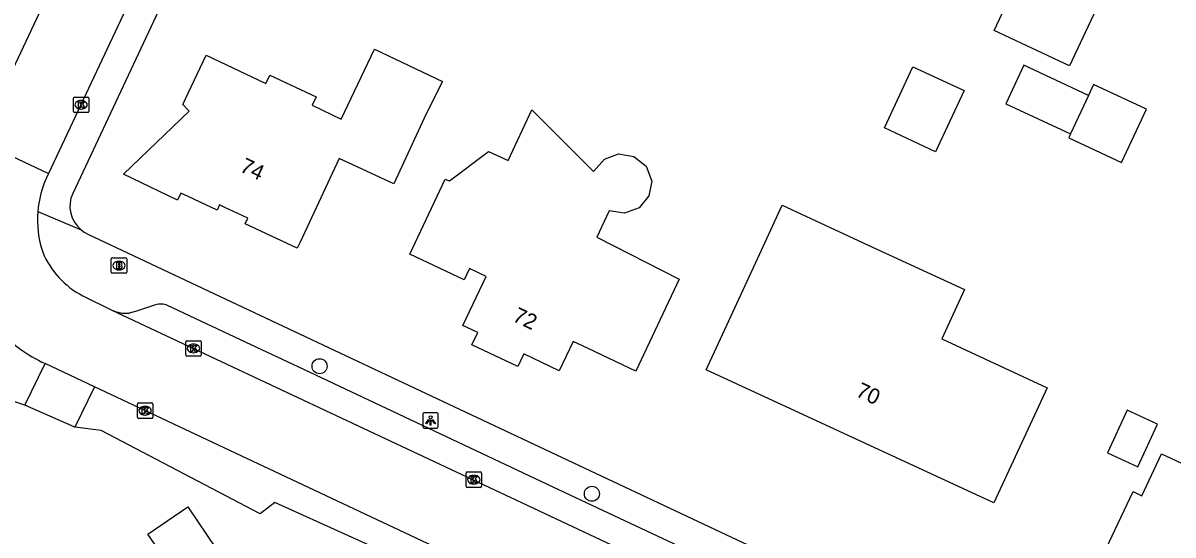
# Model space of a CAD drawing. Extents: x 158838 to 160074, y 386376 to 387776.
# Drawn here: x 159290.1 to 159364.7, y 386562.7 to 386595.9 of the extents above; entities that cross this region are included whole.
import ezdxf

# ---------------------------------------------------------------- set-up
doc = ezdxf.new("R2010")
doc.units = 0
for name, color, linetype in [('IMGEO_Berm_groen', 7, 'Continuous'), ('IMGEO_Boom', 7, 'Continuous'), ('IMGEO_Brandkraan', 7, 'Continuous'), ('IMGEO_Groenvoorziening', 7, 'Continuous'), ('IMGEO_Kolk', 7, 'Continuous'), ('IMGEO_Lichtpunt', 7, 'Continuous'), ('IMGEO_Pand', 7, 'Continuous'), ('IMGEO_Pand_nummerreeks', 7, 'Continuous'), ('IMGEO_Rijbaan_lokaal_open', 7, 'Continuous'), ('IMGEO_Voetpad_open', 7, 'Continuous')]:
    doc.layers.add(name, color=color, linetype=linetype)

msp = doc.modelspace()

# ---------------------------------------------------------------- linework, layer by layer
at = {"layer": 'IMGEO_Berm_groen'}
msp.add_lwpolyline([(159290.204, 386571.089), (159288.276, 386571.713)], dxfattribs=at)
at = {"layer": 'IMGEO_Boom'}
for centre in [(159309.333, 386573.609), (159327.006, 386565.334)]:
    msp.add_circle(centre, 0.489, dxfattribs=at)
at = {"layer": 'IMGEO_Brandkraan'}
for p, q in [((159295.816, 386579.72), (159295.816, 386580.572)), ((159295.891, 386580.646), (159296.743, 386580.646)), ((159296.304, 386580.426), (159296.329, 386580.426)), ((159296.817, 386580.572), (159296.817, 386579.72)), ((159296.743, 386579.646), (159295.891, 386579.646)), ((159296.327, 386579.866), (159296.302, 386579.866))]:
    msp.add_line(p, q, dxfattribs=at)
for points in [[(159295.816, 386579.72), (159295.816, 386580.572)], [(159295.891, 386580.646), (159296.743, 386580.646)], [(159296.817, 386580.572), (159296.817, 386579.72)], [(159296.743, 386579.646), (159295.891, 386579.646)], [(159296.164, 386580.346), (159296.164, 386579.946), (159296.377, 386579.946)], [(159296.395, 386580.346), (159296.164, 386580.346)], [(159296.343, 386580.265), (159296.289, 386580.265), (159296.289, 386580.189)], [(159296.289, 386580.189), (159296.342, 386580.189)], [(159296.351, 386580.113), (159296.289, 386580.113), (159296.289, 386580.032)], [(159296.289, 386580.032), (159296.351, 386580.032)]]:
    msp.add_lwpolyline(points, dxfattribs=at)
for centre, radius, start, end in [((159295.893, 386580.57), 0.0765, 91.55205, 178.44795), ((159295.893, 386580.57), 0.0765, 91.55205, 178.44795), ((159296.741, 386580.57), 0.0765, 1.55205, 88.44795), ((159296.741, 386580.57), 0.0765, 1.55205, 88.44795), ((159295.893, 386579.722), 0.0765, 181.55205, 268.44795), ((159295.893, 386579.722), 0.0765, 181.55205, 268.44795), ((159296.344, 386580.227), 0.0379, 267.82845, 90.93552), ((159296.352, 386580.072), 0.0404, 269.87594, 90.50774), ((159296.383, 386580.197), 0.251, 268.66757, 293.53466), ((159296.399, 386580.201), 0.145, 59.4692, 91.53667), ((159296.424, 386580.248), 0.0922, 285.51372, 58.15012), ((159296.429, 386580.056), 0.105, 301.31148, 78.98903), ((159296.741, 386579.722), 0.0765, 271.55205, 358.44795), ((159296.741, 386579.722), 0.0765, 271.55205, 358.44795)]:
    msp.add_arc(centre, radius, start, end, dxfattribs=at)
for centre, major_axis, ratio, start_param, end_param in [((159296.303, 386580.146), (-0.387, 0.002), 0.722429, 4.712389, 7.853982), ((159296.328, 386580.146), (-0.39, 0.002), 0.717154, 1.570796, 4.712389)]:
    msp.add_ellipse(centre, major_axis=major_axis, ratio=ratio, start_param=start_param, end_param=end_param, dxfattribs=at)
at = {"layer": 'IMGEO_Groenvoorziening'}
msp.add_lwpolyline([(159315.993, 386560.431), (159306.423, 386564.757), (159305.475, 386564.027), (159295.152, 386569.449), (159293.452, 386569.649)], dxfattribs=at)
at = {"layer": 'IMGEO_Kolk'}
for p, q in [((159293.357, 386590.15), (159293.357, 386591.002)), ((159293.432, 386591.076), (159294.284, 386591.076)), ((159293.845, 386590.856), (159293.87, 386590.856)), ((159294.358, 386591.002), (159294.358, 386590.15)), ((159294.284, 386590.076), (159293.432, 386590.076)), ((159293.868, 386590.296), (159293.843, 386590.296)), ((159300.65, 386574.339), (159300.65, 386575.191)), ((159300.725, 386575.265), (159301.577, 386575.265)), ((159301.651, 386575.191), (159301.651, 386574.339)), ((159301.161, 386574.485), (159301.136, 386574.485)), ((159301.138, 386575.045), (159301.163, 386575.045)), ((159301.577, 386574.265), (159300.725, 386574.265)), ((159297.507, 386570.298), (159297.507, 386571.15)), ((159297.582, 386571.224), (159298.434, 386571.224)), ((159297.995, 386571.004), (159298.02, 386571.004)), ((159298.508, 386571.15), (159298.508, 386570.298)), ((159298.434, 386570.224), (159297.582, 386570.224)), ((159298.018, 386570.444), (159297.993, 386570.444)), ((159318.843, 386565.821), (159318.843, 386566.673)), ((159318.918, 386566.747), (159319.77, 386566.747)), ((159319.331, 386566.527), (159319.356, 386566.527)), ((159319.844, 386566.673), (159319.844, 386565.821)), ((159319.77, 386565.747), (159318.918, 386565.747)), ((159319.354, 386565.967), (159319.329, 386565.967))]:
    msp.add_line(p, q, dxfattribs=at)
for points in [[(159293.357, 386590.15), (159293.357, 386591.002)], [(159293.432, 386591.076), (159294.284, 386591.076)], [(159294.358, 386591.002), (159294.358, 386590.15)], [(159294.284, 386590.076), (159293.432, 386590.076)], [(159293.678, 386590.776), (159293.801, 386590.776), (159293.801, 386590.625), (159293.931, 386590.776), (159294.095, 386590.776), (159293.949, 386590.625), (159294.102, 386590.376), (159293.95, 386590.376), (159293.865, 386590.54), (159293.801, 386590.473), (159293.801, 386590.376), (159293.678, 386590.376), (159293.678, 386590.776)], [(159300.65, 386574.339), (159300.65, 386575.191)], [(159300.725, 386575.265), (159301.577, 386575.265)], [(159301.651, 386575.191), (159301.651, 386574.339)], [(159300.971, 386574.965), (159301.094, 386574.965), (159301.094, 386574.814), (159301.224, 386574.965), (159301.388, 386574.965), (159301.242, 386574.814), (159301.395, 386574.565), (159301.243, 386574.565), (159301.158, 386574.729), (159301.094, 386574.662), (159301.094, 386574.565), (159300.971, 386574.565), (159300.971, 386574.965)], [(159301.577, 386574.265), (159300.725, 386574.265)], [(159297.507, 386570.298), (159297.507, 386571.15)], [(159297.582, 386571.224), (159298.434, 386571.224)], [(159297.828, 386570.924), (159297.951, 386570.924), (159297.951, 386570.773), (159298.081, 386570.924), (159298.245, 386570.924), (159298.099, 386570.773), (159298.252, 386570.524), (159298.1, 386570.524), (159298.015, 386570.688), (159297.951, 386570.621), (159297.951, 386570.524), (159297.828, 386570.524), (159297.828, 386570.924)], [(159298.508, 386571.15), (159298.508, 386570.298)], [(159298.434, 386570.224), (159297.582, 386570.224)], [(159318.843, 386565.821), (159318.843, 386566.673)], [(159318.918, 386566.747), (159319.77, 386566.747)], [(159319.164, 386566.447), (159319.287, 386566.447), (159319.287, 386566.296), (159319.417, 386566.447), (159319.581, 386566.447), (159319.435, 386566.296), (159319.588, 386566.047), (159319.436, 386566.047), (159319.351, 386566.211), (159319.287, 386566.144), (159319.287, 386566.047), (159319.164, 386566.047), (159319.164, 386566.447)], [(159319.844, 386566.673), (159319.844, 386565.821)], [(159319.77, 386565.747), (159318.918, 386565.747)]]:
    msp.add_lwpolyline(points, dxfattribs=at)
for centre, start, end in [((159293.434, 386591), 91.55205, 178.44795), ((159293.434, 386591), 91.55205, 178.44795), ((159294.282, 386591), 1.55205, 88.44795), ((159294.282, 386591), 1.55205, 88.44795), ((159293.434, 386590.152), 181.55205, 268.44795), ((159293.434, 386590.152), 181.55205, 268.44795), ((159294.282, 386590.152), 271.55205, 358.44795), ((159294.282, 386590.152), 271.55205, 358.44795), ((159300.727, 386575.189), 91.55205, 178.44795), ((159300.727, 386575.189), 91.55205, 178.44795), ((159301.575, 386575.189), 1.55205, 88.44795), ((159301.575, 386575.189), 1.55205, 88.44795), ((159300.727, 386574.341), 181.55205, 268.44795), ((159300.727, 386574.341), 181.55205, 268.44795), ((159301.575, 386574.341), 271.55205, 358.44795), ((159301.575, 386574.341), 271.55205, 358.44795), ((159297.584, 386571.148), 91.55205, 178.44795), ((159297.584, 386571.148), 91.55205, 178.44795), ((159298.432, 386571.148), 1.55205, 88.44795), ((159298.432, 386571.148), 1.55205, 88.44795), ((159297.584, 386570.3), 181.55205, 268.44795), ((159297.584, 386570.3), 181.55205, 268.44795), ((159298.432, 386570.3), 271.55205, 358.44795), ((159298.432, 386570.3), 271.55205, 358.44795), ((159318.92, 386566.671), 91.55205, 178.44795), ((159318.92, 386566.671), 91.55205, 178.44795), ((159319.768, 386566.671), 1.55205, 88.44795), ((159319.768, 386566.671), 1.55205, 88.44795), ((159318.92, 386565.823), 181.55205, 268.44795), ((159318.92, 386565.823), 181.55205, 268.44795), ((159319.768, 386565.823), 271.55205, 358.44795), ((159319.768, 386565.823), 271.55205, 358.44795)]:
    msp.add_arc(centre, 0.0765, start, end, dxfattribs=at)
for centre, major_axis, ratio, start_param, end_param in [((159293.844, 386590.576), (-0.387, 0.002), 0.722429, 4.712389, 7.853982), ((159293.869, 386590.576), (-0.39, 0.002), 0.717154, 1.570796, 4.712389), ((159301.137, 386574.765), (-0.387, 0.002), 0.722429, 4.712389, 7.853982), ((159301.162, 386574.765), (-0.39, 0.002), 0.717154, 1.570796, 4.712389), ((159297.994, 386570.724), (-0.387, 0.002), 0.722429, 4.712389, 7.853982), ((159298.019, 386570.724), (-0.39, 0.002), 0.717154, 1.570796, 4.712389), ((159319.33, 386566.247), (-0.387, 0.002), 0.722429, 4.712389, 7.853982), ((159319.355, 386566.247), (-0.39, 0.002), 0.717154, 1.570796, 4.712389)]:
    msp.add_ellipse(centre, major_axis=major_axis, ratio=ratio, start_param=start_param, end_param=end_param, dxfattribs=at)
at = {"layer": 'IMGEO_Lichtpunt'}
for p, q in [((159316.038, 386570.495), (159316.038, 386569.688)), ((159316.038, 386570.495), (159316.038, 386569.688)), ((159316.94, 386570.59), (159316.132, 386570.59)), ((159316.94, 386570.59), (159316.132, 386570.59)), ((159317.034, 386569.688), (159317.034, 386570.495)), ((159317.034, 386569.688), (159317.034, 386570.495)), ((159316.132, 386569.594), (159316.94, 386569.594)), ((159316.132, 386569.594), (159316.94, 386569.594))]:
    msp.add_line(p, q, dxfattribs=at)
for points in [[(159316.412, 386570.159), (159316.451, 386570.131), (159316.263, 386569.869), (159316.225, 386569.896), (159316.412, 386570.159)], [(159316.514, 386570.111), (159316.561, 386570.111), (159316.561, 386569.789), (159316.514, 386569.789), (159316.514, 386570.111)], [(159316.624, 386570.131), (159316.662, 386570.158), (159316.849, 386569.896), (159316.81, 386569.868), (159316.624, 386570.131)]]:
    msp.add_lwpolyline(points, dxfattribs=at)
msp.add_circle((159316.537, 386570.293), 0.0994, dxfattribs=at)
for centre, start, end in [((159316.132, 386570.495), 90, 180), ((159316.132, 386570.495), 90, 180), ((159316.94, 386570.495), 0, 90), ((159316.94, 386570.495), 0, 90), ((159316.132, 386569.688), 180, 270), ((159316.132, 386569.688), 180, 270), ((159316.94, 386569.688), 270, 0), ((159316.94, 386569.688), 270, 360)]:
    msp.add_arc(centre, 0.0946, start, end, dxfattribs=at)
at = {"layer": 'IMGEO_Pand'}
for points in [[(159358, 386593.116), (159353.123, 386595.392), (159356.161, 386601.904), (159347.942, 386605.74), (159351.96, 386614.293), (159356.458, 386612.18), (159355.927, 386611.045), (159355.32, 386609.746), (159358.046, 386608.482), (159358.679, 386609.842), (159364.569, 386607.1), (159358, 386593.116)], [(159314.156, 386585.452), (159310.611, 386587.087), (159308.064, 386581.661), (159307.883, 386581.276), (159304.51, 386582.859), (159304.683, 386583.209), (159304.312, 386583.385), (159303.181, 386583.921), (159302.837, 386584.084), (159302.677, 386583.741), (159300.795, 386584.622), (159300.325, 386584.845), (159300.103, 386584.386), (159296.615, 386586.075), (159300.875, 386590.164), (159300.455, 386590.591), (159300.81, 386591.341), (159301.977, 386593.803), (159305.854, 386591.966), (159306.111, 386592.508), (159309.116, 386591.096), (159308.854, 386590.544), (159310.743, 386589.649), (159312.888, 386594.177), (159317.317, 386592.079), (159316.25, 386589.992), (159314.156, 386585.452)], [(159359.238, 386591.187), (159355.044, 386593.145), (159353.874, 386590.639), (159358.068, 386588.682)], [(159345.988, 386589.084), (159347.838, 386593.049), (159351.165, 386591.495), (159349.315, 386587.531), (159345.988, 386589.084)], [(159358.068, 386588.682), (159357.95, 386588.428), (159361.38, 386586.828), (159362.994, 386590.288), (159359.565, 386591.889), (159359.238, 386591.187)], [(159359.238, 386591.187), (159358.068, 386588.682)], [(159329.848, 386573.285), (159326.764, 386574.751), (159325.784, 386575.219), (159324.891, 386573.318), (159322.579, 386574.404), (159322.2, 386573.589), (159319.214, 386574.998), (159319.597, 386575.809), (159318.639, 386576.258), (159320.148, 386579.426), (159319.06, 386579.946), (159318.714, 386579.214), (159315.19, 386580.877), (159317.494, 386585.761), (159317.642, 386585.692), (159317.766, 386585.635), (159320.294, 386587.55), (159321.575, 386586.956), (159323.101, 386590.25), (159327.115, 386586.251), (159327.823, 386587.048), (159328.744, 386587.39), (159329.731, 386587.223), (159330.525, 386586.585), (159330.886, 386585.627), (159330.696, 386584.658), (159330.07, 386583.888), (159329.119, 386583.541), (159328.136, 386583.703), (159327.964, 386583.338), (159327.325, 386581.989), (159332.664, 386579.25), (159329.848, 386573.285)], [(159351.19, 386578.58), (159349.711, 386575.385), (159356.553, 386572.218), (159353.092, 386564.74), (159334.42, 386573.381), (159337.881, 386580.859), (159339.36, 386584.054), (159345.227, 386581.339), (159351.19, 386578.58)], [(159361.748, 386570.768), (159360.458, 386567.982), (159362.428, 386567.071), (159363.718, 386569.856), (159361.748, 386570.768)], [(159375.17, 386563.748), (159374.759, 386562.873), (159376.049, 386562.268), (159371.134, 386551.805), (159367.88, 386553.334), (159368.066, 386553.748), (159366.221, 386554.606), (159366.612, 386555.412), (159363.924, 386556.661), (159363.559, 386555.849), (159363.267, 386555.981), (159363.413, 386556.269), (159358.804, 386558.439), (159362.137, 386565.474), (159362.705, 386565.207), (159363.983, 386567.931), (159365.273, 386567.326), (159365.683, 386568.201)], [(159298.191, 386562.717), (159300.777, 386564.478), (159302.625, 386561.766), (159300.039, 386560.005), (159298.191, 386562.717)]]:
    msp.add_lwpolyline(points, dxfattribs=at)
at = {"layer": 'IMGEO_Rijbaan_lokaal_open'}
for points in [[(159317.337, 386640.495), (159308.358, 386621.447), (159300.916, 386605.621), (159291.751, 386586.124)], [(159305.139, 386626.281), (159289.415, 386592.84), (159287.367, 386588.415)], [(159287.279, 386588.226), (159291.751, 386586.124)], [(159291.751, 386586.124), (159291.615, 386585.834)], [(159291.114, 386584.184), (159291.076, 386583.919), (159291.048, 386583.652)], [(159293.961, 386578.18), (159295.852, 386577.254)], [(159295.852, 386577.254), (159321.741, 386565.098), (159360.254, 386546.992), (159382.422, 386536.598), (159382.972, 386536.339)], [(159294.718, 386572.279), (159291.526, 386573.78)], [(159316.71, 386561.942), (159294.718, 386572.279)]]:
    msp.add_lwpolyline(points, dxfattribs=at)
for centre, radius, start, end in [((159297.567, 386583.126), 6.539, 155.53342, 170.68618), ((159297.616, 386583.105), 6.59, 175.23653, 198.53281), ((159296.545, 386583.152), 5.603, 202.4755, 242.54173), ((159295.513, 386582.444), 9.537, 222.14677, 245.28758)]:
    msp.add_arc(centre, radius, start, end, dxfattribs=at)
at = {"layer": 'IMGEO_Voetpad_open'}
for points in [[(159317.997, 386637.363), (159308.288, 386616.654), (159298.562, 386595.977), (159293.313, 386584.825)], [(159291.048, 386583.652), (159293.857, 386582.459)], [(159293.857, 386582.459), (159294.064, 386582.31), (159294.288, 386582.188), (159316.242, 386571.848), (159355.883, 386553.199), (159361.891, 386550.365), (159390.458, 386536.952), (159425.102, 386520.721)], [(159298.683, 386577.6), (159297.396, 386577.16), (159296.983, 386577.061)], [(159383.723, 386537.942), (159358.772, 386549.664), (159355.359, 386551.266), (159352.653, 386552.537), (159349.241, 386554.139), (159325.961, 386565.07), (159322.56, 386566.673), (159308.304, 386573.391), (159304.902, 386574.994), (159299.466, 386577.556)], [(159290.204, 386571.089), (159291.526, 386573.78)], [(159294.718, 386572.279), (159293.452, 386569.649)], [(159293.452, 386569.649), (159290.204, 386571.089)]]:
    msp.add_lwpolyline(points, dxfattribs=at)
for centre, radius, start, end in [((159295.125, 386583.996), 1.993, 155.4198, 230.47745), ((159299.012, 386576.467), 1.179, 67.36525, 106.20214), ((159296.773, 386579.239), 2.189, 245.11948, 275.51255)]:
    msp.add_arc(centre, radius, start, end, dxfattribs=at)

# ---------------------------------------------------------------- texts
at = {"layer": 'IMGEO_Pand_nummerreeks'}
for s, rotation, p in [('74', 334.63915, (159304.092, 386586.277)), ('72', 334.73884, (159321.798, 386576.571)), ('70', 335.16801, (159344.067, 386571.693))]:
    msp.add_text(s, height=1, rotation=rotation, dxfattribs=at).set_placement(p)

doc.saveas('drawing.dxf')
